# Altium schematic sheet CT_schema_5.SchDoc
size 368 x 245 mm
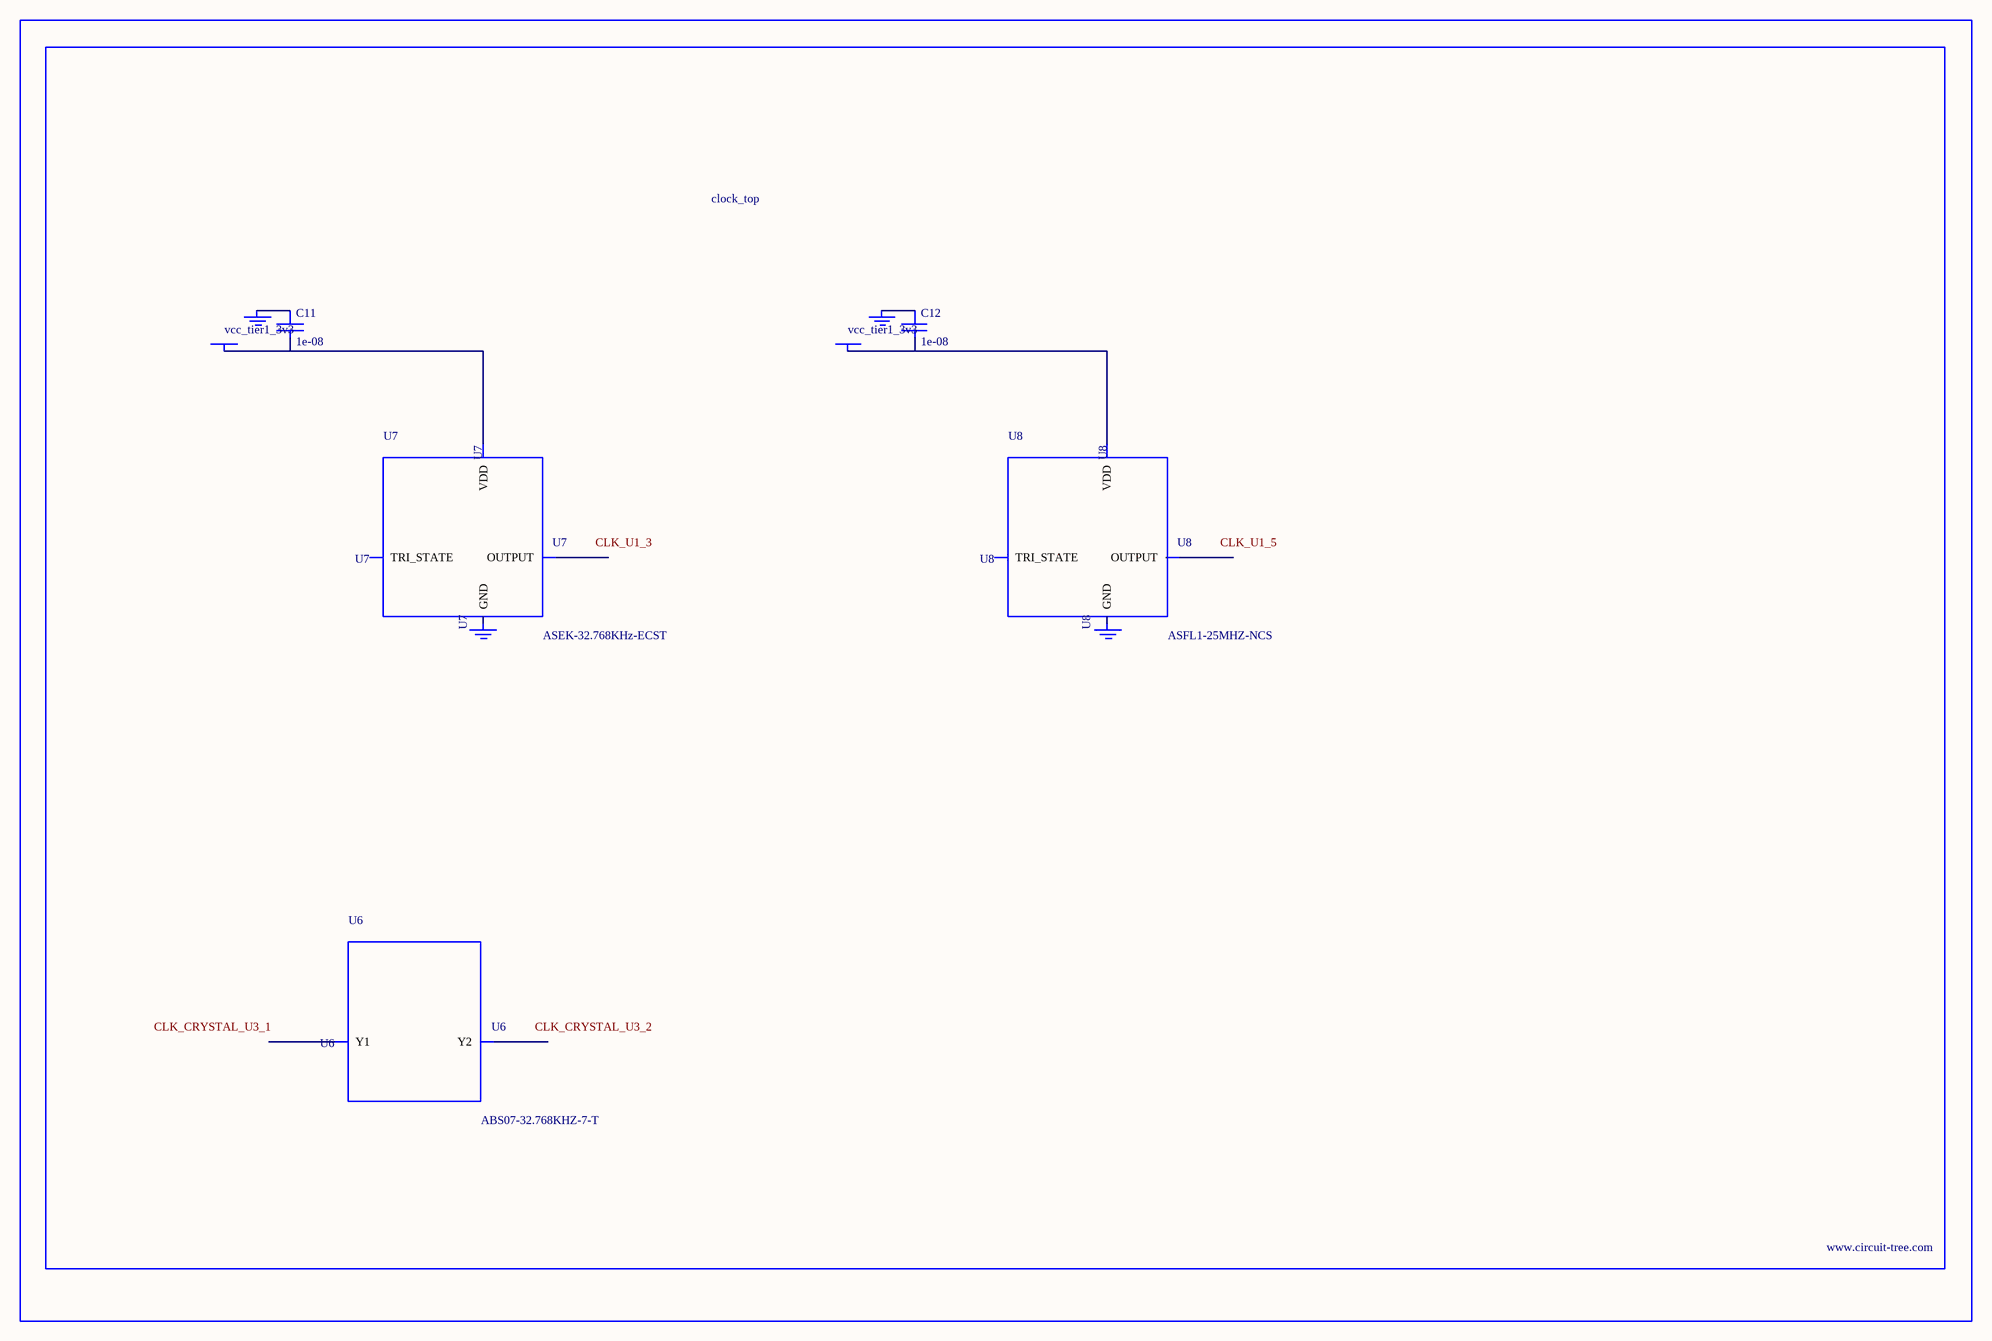
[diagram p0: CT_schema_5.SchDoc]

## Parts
BORDER4  (no value)
C11  1e-08  [C0402]
C12  1e-08  [C0402]
GND_INSTANCE_4_0  (no value)
GND_INSTANCE_4_1  (no value)
GND_INSTANCE_4_2  (no value)
GND_INSTANCE_4_3  (no value)
POWER_INSTANCE_4_0  vcc_tier1_3v3
POWER_INSTANCE_4_1  vcc_tier1_3v3
U6  ABS07-32.768KHZ-7-T  [ABS07-32.768KHZ-7-T]
U7  ASEK-32.768KHz-ECST  [ASEK]
U8  ASFL1-25MHZ-NCS  [ASFL1]

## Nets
NetC11_1: C11.1 GND_INSTANCE_4_0.0(GND)
NetC11_2: C11.2 POWER_INSTANCE_4_0.0(PWR) U7.4(VDD)
NetC12_1: C12.1 GND_INSTANCE_4_2.0(GND)
NetC12_2: C12.2 POWER_INSTANCE_4_1.0(PWR) U8.4(VDD)

Not connected (* = marked no-connect by the designer): GND_INSTANCE_4_1 0(GND); GND_INSTANCE_4_3 0(GND); U6 1(Y1) 2(Y2); U7 1(TRI_STATE) 2(GND) 3(OUTPUT); U8 1(TRI_STATE) 2(GND) 3(OUTPUT)

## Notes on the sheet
- Labels drawn without touching a wire or pin: CLK_CRYSTAL_U3_1, CLK_CRYSTAL_U3_2, CLK_U1_3, CLK_U1_5

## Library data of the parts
BORDER4 = BORDER_PAGE4
C11 C12 = C0402C103K3RAC
GND_INSTANCE_4_0-GND_INSTANCE_4_3 = GND
POWER_INSTANCE_4_0 POWER_INSTANCE_4_1 = PWR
